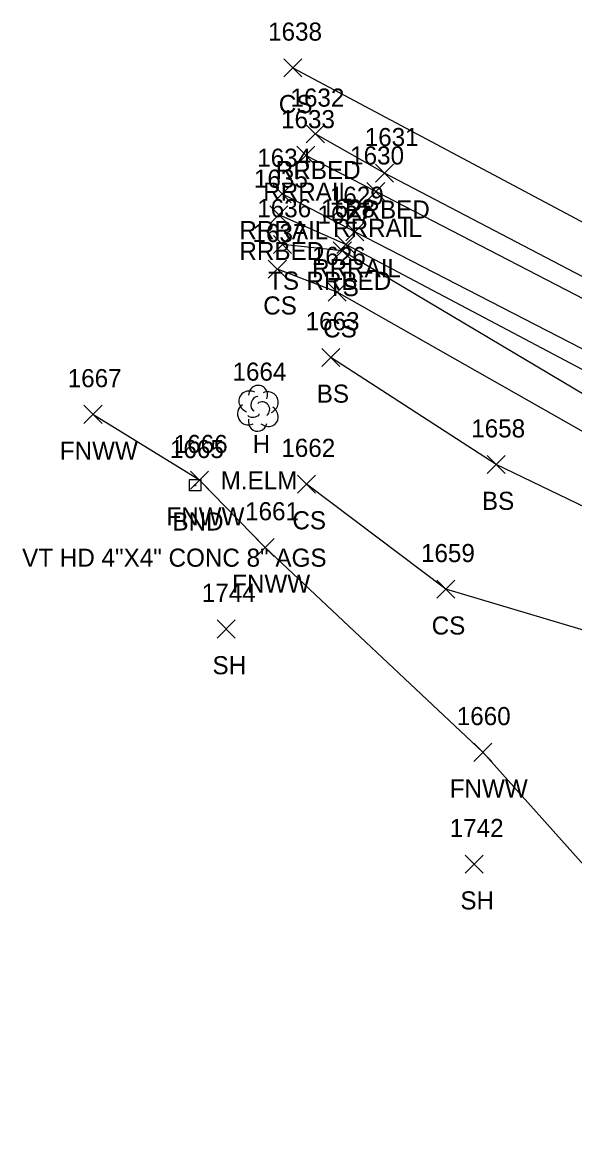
# Model space of a CAD drawing. Extents: x 1443960 to 1446865, y 610387 to 616706.
# Drawn here: x 1446314.4 to 1446375.4, y 611170.6 to 611293.5 of the extents above; entities that cross this region are included whole.
import ezdxf

# ---------------------------------------------------------------- set-up
doc = ezdxf.new("R2010")
doc.units = 0
for name, color, linetype in [('L_A', 7, 'Continuous'), ('L_C', 7, 'Continuous'), ('L_I', 7, 'Continuous'), ('L_TIC', 7, 'Continuous'), ('LELB', 7, 'Continuous'), ('LFNC', 7, 'Continuous'), ('LTD', 7, 'Continuous'), ('M_A', 7, 'Continuous'), ('M_C', 7, 'Continuous'), ('M_I', 7, 'Continuous'), ('MHBP', 7, 'Continuous'), ('R_A', 7, 'Continuous'), ('R_I', 7, 'Continuous'), ('R_TIC', 7, 'Continuous'), ('RR', 7, 'Continuous'), ('RRB', 7, 'Continuous')]:
    doc.layers.add(name, color=color, linetype=linetype)

msp = doc.modelspace()

# ---------------------------------------------------------------- linework, layer by layer
at = {"layer": 'L_TIC'}
for points in [[(1446343.24, 611287.47), (1446345.24, 611289.47)], [(1446345.24, 611287.47), (1446343.24, 611289.47)], [(1446342.09, 611267.96), (1446344.09, 611269.96)], [(1446344.09, 611267.96), (1446342.09, 611269.96)], [(1446348.69, 611267.25), (1446350.69, 611269.25)], [(1446350.69, 611267.25), (1446348.69, 611269.25)], [(1446341.52, 611265.22), (1446343.52, 611267.22)], [(1446343.52, 611265.22), (1446341.52, 611267.22)], [(1446348.13, 611262.69), (1446350.13, 611264.69)], [(1446350.13, 611262.69), (1446348.13, 611264.69)], [(1446347.43, 611255.48), (1446349.43, 611257.48)], [(1446349.43, 611255.48), (1446347.43, 611257.48)], [(1446321.16, 611249.19), (1446323.16, 611251.19)], [(1446323.16, 611249.19), (1446321.16, 611251.19)], [(1446365.67, 611243.64), (1446367.67, 611245.64)], [(1446367.67, 611243.64), (1446365.67, 611245.64)], [(1446332.92, 611241.92), (1446334.92, 611243.92)], [(1446334.92, 611241.92), (1446332.92, 611243.92)], [(1446344.74, 611241.49), (1446346.74, 611243.49)], [(1446346.74, 611241.49), (1446344.74, 611243.49)], [(1446340.18, 611234.49), (1446342.18, 611236.49)], [(1446342.18, 611234.49), (1446340.18, 611236.49)], [(1446360.12, 611229.87), (1446362.12, 611231.87)], [(1446362.12, 611229.87), (1446360.12, 611231.87)], [(1446335.88, 611225.48), (1446337.88, 611227.48)], [(1446337.88, 611225.48), (1446335.88, 611227.48)], [(1446364.2, 611211.86), (1446366.2, 611213.86)], [(1446366.2, 611211.86), (1446364.2, 611213.86)], [(1446363.24, 611199.5), (1446365.24, 611201.5)], [(1446365.24, 611199.5), (1446363.24, 611201.5)]]:
    msp.add_lwpolyline(points, dxfattribs=at)
at = {"layer": 'LELB'}
for points in [[(1446344.24, 611288.47), (1446379.4, 611269.73), (1446415.39, 611251.12), (1446451.44, 611233.03), (1446488.32, 611214.89), (1446522.86, 611197.29), (1446554.41, 611180.54)], [(1446548.85, 610888.19), (1446553.44, 610932.22), (1446554.61, 610954.43), (1446557.18, 610985.54), (1446561.83, 611026.07), (1446565.58, 611053.66), (1446570.69, 611096.92), (1446573.29, 611130.79), (1446568.51, 611145), (1446569.91, 611148.66), (1446564.88, 611156.7), (1446536.84, 611169.59), (1446508.69, 611183.48), (1446466.55, 611207.56), (1446427.27, 611227.8), (1446388.8, 611245), (1446349.69, 611268.25), (1446343.09, 611268.96)], [(1446552.43, 611156.81), (1446533.31, 611167.82), (1446507.38, 611180.73), (1446464.69, 611203.31), (1446425.68, 611223.52), (1446387.19, 611242.09), (1446349.13, 611263.69), (1446342.52, 611266.22)], [(1446545.33, 610990.77), (1446549.45, 611028.52), (1446549.03, 611055.59), (1446553.29, 611104.25), (1446542.01, 611115.66), (1446540.05, 611127.24), (1446544.04, 611129.96), (1446551.51, 611136.49), (1446553.27, 611138.91), (1446550.53, 611149.51), (1446533.12, 611159.93), (1446498.33, 611176.52), (1446468.4, 611193.46), (1446432.91, 611211.11), (1446396.49, 611230.29), (1446366.67, 611244.64), (1446348.43, 611256.48)], [(1446530.86, 610991.05), (1446536.61, 611027.8), (1446530.46, 611055.9), (1446528.01, 611097.29), (1446529.9, 611126.45), (1446531.13, 611139.44), (1446489.18, 611159.91), (1446465.02, 611182.42), (1446422.58, 611193.97), (1446390.63, 611222.09), (1446361.12, 611230.87), (1446345.74, 611242.49)]]:
    msp.add_lwpolyline(points, dxfattribs=at)
at = {"layer": 'LFNC'}
for points in [[(1446365.2, 611212.86), (1446341.18, 611235.49), (1446333.92, 611242.92), (1446322.16, 611250.19)], [(1446365.2, 611212.86), (1446396.85, 611177.46)]]:
    msp.add_lwpolyline(points, dxfattribs=at)
at = {"layer": 'LTD'}
msp.add_line((1446340.35, 611250.91), (1446340.35, 611250.91), dxfattribs=at)
msp.add_line((1446340.35, 611250.91), (1446340.35, 611250.91), dxfattribs=at)
msp.add_arc((1446340.4, 611252.34), 1.05, 335.5272, 180.9563, dxfattribs=at)
for centre, major_axis, ratio, start_param, end_param in [((1446339.56, 611251.57), (1.21, -0.51), 0.895232, 1.570796, 4.712389), ((1446340.15, 611251.36), (-0.208, -0.792), 0.645439, 3.141593, 6.283185), ((1446341.4, 611251.49), (-1.14, -0.48), 0.949671, 1.570796, 4.712389), ((1446339.27, 611250.2), (0.58, -1.04), 0.959034, 3.141593, 6.283185), ((1446340.85, 611250.74), (-0.5, 0.667), 0.989748, 3.141593, 6.283185), ((1446341.35, 611250.07), (-1.09, 0.79), 0.841452, 1.570796, 4.712389), ((1446340.35, 611249.41), (0.26, 1.06), 0.942809, 1.570796, 4.712389), ((1446339.9, 611250.16), (-0.625, -0.083), 0.423636, 0, 3.141593)]:
    msp.add_ellipse(centre, major_axis=major_axis, ratio=ratio, start_param=start_param, end_param=end_param, dxfattribs=at)
at = {"layer": 'MHBP'}
msp.add_lwpolyline([(1446332.82, 611242.99), (1446334.07, 611242.99), (1446334.07, 611241.74), (1446332.82, 611241.74)], close=True, dxfattribs=at)
msp.add_circle((1446333.44, 611242.36), 0.0833, dxfattribs=at)
at = {"layer": 'R_TIC'}
for points in [[(1446345.71, 611280.18), (1446347.71, 611282.18)], [(1446347.71, 611280.18), (1446345.71, 611282.18)], [(1446344.67, 611277.8), (1446346.67, 611279.8)], [(1446346.67, 611277.8), (1446344.67, 611279.8)], [(1446353.34, 611275.82), (1446355.34, 611277.82)], [(1446355.34, 611275.82), (1446353.34, 611277.82)], [(1446342.04, 611273.54), (1446344.04, 611275.54)], [(1446344.04, 611273.54), (1446342.04, 611275.54)], [(1446352.39, 611273.79), (1446354.39, 611275.79)], [(1446354.39, 611273.79), (1446352.39, 611275.79)], [(1446341.68, 611271.23), (1446343.68, 611273.23)], [(1446343.68, 611271.23), (1446341.68, 611273.23)], [(1446350.07, 611269.34), (1446352.07, 611271.34)], [(1446352.07, 611269.34), (1446350.07, 611271.34)], [(1446349.09, 611267.94), (1446351.09, 611269.94)], [(1446351.09, 611267.94), (1446349.09, 611269.94)]]:
    msp.add_lwpolyline(points, dxfattribs=at)
at = {"layer": 'RR'}
for points in [[(1446830.8, 611028.51), (1446813.8, 611037.34), (1446780.13, 611054.63), (1446766.6, 611061.72), (1446723.16, 611084.18), (1446681.83, 611105.5), (1446667.65, 611112.72), (1446650.45, 611121.75), (1446635.82, 611129.05), (1446620.36, 611137.27), (1446611.04, 611142.08), (1446598.97, 611148.35), (1446587.47, 611154.32), (1446577.27, 611159.61), (1446545.1, 611176.06), (1446537.95, 611179.67), (1446530.32, 611183.72), (1446472.23, 611213.59), (1446430.68, 611235.02), (1446393.22, 611254.19), (1446353.39, 611274.79), (1446345.67, 611278.8)], [(1446830.61, 611022.91), (1446812, 611032.72), (1446777.67, 611050.48), (1446764.9, 611057.05), (1446720.8, 611079.76), (1446679.61, 611101.04), (1446672.6, 611104.75), (1446648.09, 611117.4), (1446634.05, 611124.73), (1446619.04, 611132.42), (1446610.71, 611136.75), (1446598.39, 611142.94), (1446586.96, 611148.93), (1446576.92, 611154.08), (1446541.41, 611172.48), (1446511.36, 611187.89), (1446469.88, 611209.21), (1446428.54, 611230.42), (1446391.04, 611249.76), (1446351.07, 611270.34), (1446343.04, 611274.54)]]:
    msp.add_lwpolyline(points, dxfattribs=at)
at = {"layer": 'RRB'}
for points in [[(1446569.99, 611168.04), (1446545.96, 611178.46), (1446513.02, 611195.82), (1446473.29, 611215.85), (1446431.72, 611237.21), (1446394.07, 611256.06), (1446354.34, 611276.82), (1446346.71, 611281.18)], [(1446564.88, 611156.7), (1446537.51, 611171.94), (1446510.38, 611186.08), (1446466.95, 611208.66), (1446427.98, 611228.69), (1446390.24, 611247.7), (1446350.09, 611268.94), (1446342.68, 611272.23)]]:
    msp.add_lwpolyline(points, dxfattribs=at)

# ---------------------------------------------------------------- texts
at = {"layer": 'L_A'}
for s, p in [('CS', (1446342.68, 611283.47)), ('TS', (1446341.5, 611263.96)), ('TS', (1446348.1, 611263.25)), ('CS', (1446340.96, 611261.22)), ('CS', (1446347.57, 611258.69)), ('BS', (1446346.87, 611251.48)), ('FNWW', (1446318.5, 611245.19)), ('H', (1446339.79, 611245.91)), ('BS', (1446365.11, 611239.64)), ('FNWW', (1446330.27, 611237.92)), ('CS', (1446344.18, 611237.49)), ('FNWW', (1446337.53, 611230.49)), ('CS', (1446359.56, 611225.87)), ('SH', (1446335.36, 611221.48)), ('FNWW', (1446361.55, 611207.86)), ('SH', (1446362.73, 611195.5))]:
    msp.add_text(s, height=2, dxfattribs=at).set_placement(p)
at = {"layer": 'L_C'}
msp.add_text('M.ELM', height=2, dxfattribs=at).set_placement((1446336.26, 611241.91))
at = {"layer": 'L_I'}
for s, p in [('1638', (1446341.5, 611291.47)), ('1636', (1446340.3, 611271.96)), ('1627', (1446346.95, 611271.25)), ('1637', (1446339.78, 611269.22)), ('1626', (1446346.33, 611266.69)), ('1663', (1446345.64, 611259.48)), ('1664', (1446337.57, 611253.91)), ('1667', (1446319.37, 611253.19)), ('1658', (1446363.93, 611247.64)), ('1666', (1446331.08, 611245.92)), ('1662', (1446342.96, 611245.49)), ('1661', (1446338.96, 611238.49)), ('1659', (1446358.38, 611233.87)), ('1744', (1446334.18, 611229.48)), ('1660', (1446362.33, 611215.86)), ('1742', (1446361.55, 611203.5))]:
    msp.add_text(s, height=2, dxfattribs=at).set_placement(p)
at = {"layer": 'M_A'}
msp.add_text('BND', height=2, dxfattribs=at).set_placement((1446330.93, 611237.36))
at = {"layer": 'M_C'}
msp.add_text('VT HD 4"X4" CONC 8" AGS', height=2, dxfattribs=at).set_placement((1446314.34, 611233.36))
at = {"layer": 'M_I'}
msp.add_text('1665', height=2, dxfattribs=at).set_placement((1446330.66, 611245.36))
at = {"layer": 'R_A'}
for s, p in [('RRBED', (1446342.35, 611276.18)), ('RRRAIL', (1446340.96, 611273.8)), ('RRBED', (1446349.99, 611271.82)), ('RRRAIL', (1446338.33, 611269.54)), ('RRRAIL', (1446348.68, 611269.79)), ('RRBED', (1446338.33, 611267.23)), ('RRRAIL', (1446346.36, 611265.34)), ('RRBED', (1446345.73, 611263.94))]:
    msp.add_text(s, height=2, dxfattribs=at).set_placement(p)
at = {"layer": 'R_I'}
for s, p in [('1632', (1446343.97, 611284.18)), ('1633', (1446342.93, 611281.8)), ('1631', (1446352.17, 611279.82)), ('1634', (1446340.3, 611277.54)), ('1630', (1446350.56, 611277.79)), ('1635', (1446339.94, 611275.23)), ('1629', (1446348.32, 611273.34)), ('1628', (1446347.35, 611271.94))]:
    msp.add_text(s, height=2, dxfattribs=at).set_placement(p)

doc.saveas('drawing.dxf')
